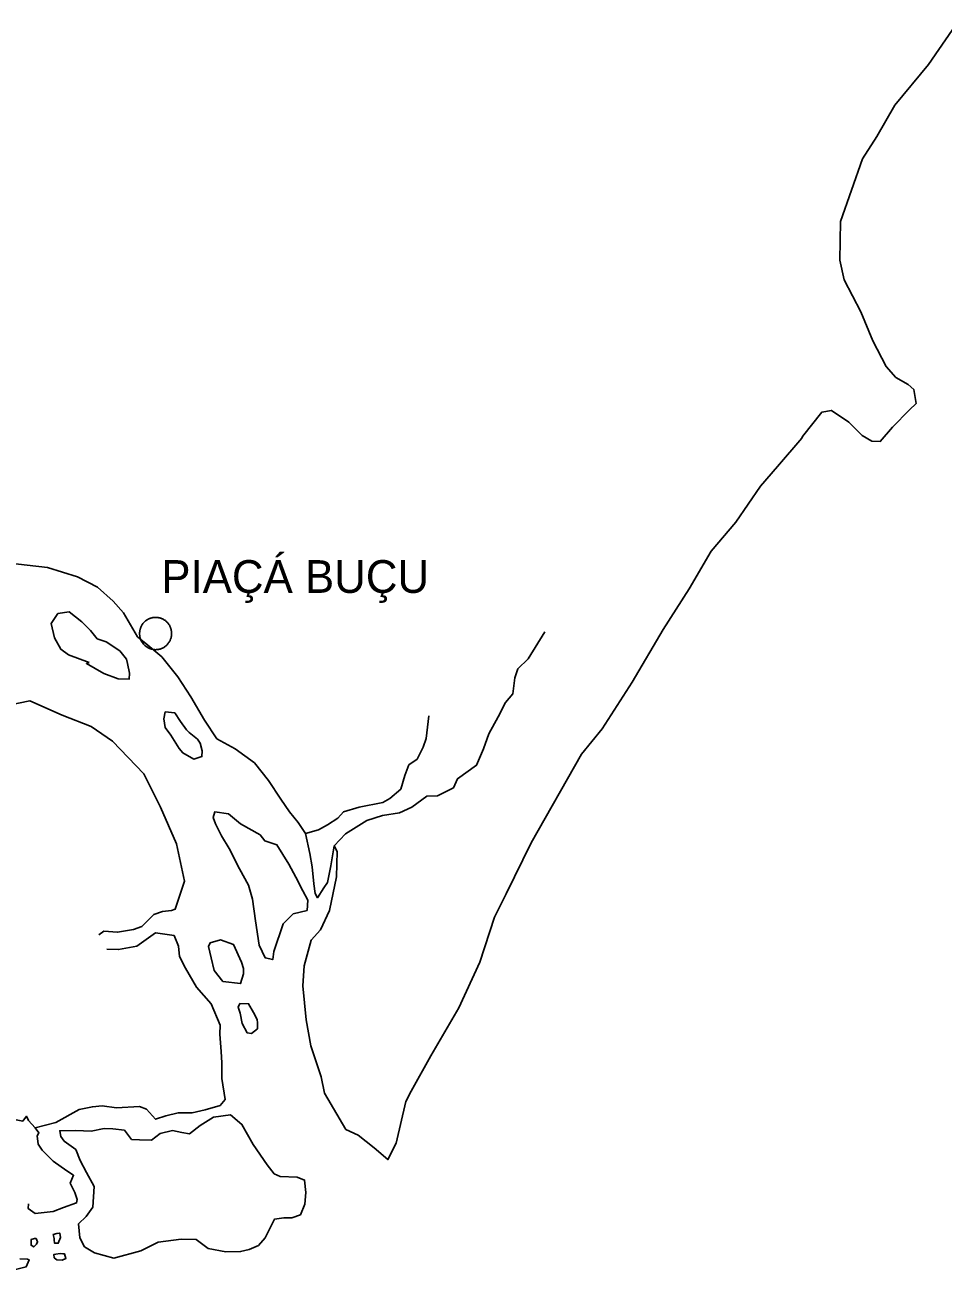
# Model space of a CAD drawing. Extents: x 662444 to 1640468, y 7452018 to 9606170.
# Drawn here: x 1438495 to 1457530, y 8823808 to 8849673 of the extents above; entities that cross this region are included whole.
import ezdxf

# ---------------------------------------------------------------- set-up
doc = ezdxf.new("R2010")
doc.units = 0
doc.layers.add('Level 1', color=7, linetype='Continuous')
doc.layers.add('Level 3', color=7, linetype='Continuous')

msp = doc.modelspace()

# ---------------------------------------------------------------- linework, layer by layer
at = {"layer": 'Level 1'}
for points in [[(1455855, 8841158), (1456051, 8841041), (1456229, 8841036), (1456480, 8841331), (1456834, 8841690), (1456970, 8841821), (1456923, 8842113), (1456804, 8842217), (1456553, 8842358), (1456349, 8842587), (1456075, 8843121), (1455826, 8843720), (1455479, 8844390), (1455390, 8844795), (1455401, 8845600), (1455858, 8846896), (1456159, 8847358), (1456531, 8848008), (1457230, 8848850), (1457795, 8849673)], [(1437449, 8838596), (1438961, 8838421), (1439586, 8838225), (1440001, 8838013), (1440325, 8837724), (1440540, 8837483), (1440826, 8836984), (1441042, 8836810), (1441335, 8836567), (1441667, 8836156), (1441932, 8835735), (1442218, 8835257), (1442473, 8834870), (1442854, 8834658), (1443256, 8834368), (1443545, 8834002), (1443800, 8833615), (1443981, 8833353), (1444163, 8833135), (1444312, 8832907), (1444400, 8832491), (1444448, 8832210), (1444483, 8831863), (1444510, 8831661), (1444563, 8831570), (1444691, 8831779), (1444771, 8831888), (1444836, 8832233), (1444903, 8832645), (1444966, 8832532), (1444952, 8832006), (1444811, 8831306), (1444623, 8830908), (1444428, 8830690), (1444281, 8830157), (1444259, 8829744), (1444328, 8829038), (1444424, 8828498), (1444638, 8827855), (1444706, 8827517), (1445151, 8826767), (1445402, 8826648), (1445738, 8826382), (1446019, 8826139), (1446194, 8826481), (1446395, 8827348), (1446501, 8827557), (1446908, 8828295), (1447489, 8829286), (1447925, 8830236), (1448227, 8831167), (1448473, 8831652), (1448990, 8832712), (1450037, 8834551), (1450461, 8835076), (1451085, 8836043), (1451724, 8837133), (1452268, 8837979), (1452722, 8838761), (1453236, 8839362), (1453744, 8840109), (1454099, 8840513), (1454602, 8841103), (1454614, 8841136), (1455016, 8841640), (1455216, 8841679), (1455575, 8841434), (1455855, 8841158)], [(1439826, 8836452), (1439398, 8836609), (1439236, 8836725), (1439109, 8836963), (1439040, 8837256), (1439178, 8837465), (1439412, 8837503), (1439672, 8837295), (1439855, 8837111), (1439994, 8836939), (1440181, 8836878), (1440463, 8836692), (1440603, 8836520), (1440622, 8836430), (1440661, 8836228), (1440658, 8836105), (1440425, 8836111), (1440130, 8836220), (1439770, 8836431), (1439826, 8836452)], [(1441536, 8837043), (1441536, 8837054), (1441535, 8837066), (1441534, 8837077), (1441534, 8837090), (1441532, 8837101), (1441530, 8837112), (1441528, 8837125), (1441525, 8837136), (1441522, 8837147), (1441519, 8837158), (1441515, 8837168), (1441511, 8837180), (1441507, 8837191), (1441501, 8837201), (1441496, 8837211), (1441490, 8837222), (1441484, 8837232), (1441478, 8837241), (1441471, 8837251), (1441464, 8837260), (1441457, 8837270), (1441449, 8837278), (1441441, 8837287), (1441433, 8837295), (1441424, 8837303), (1441416, 8837310), (1441406, 8837318), (1441397, 8837325), (1441387, 8837331), (1441378, 8837338), (1441368, 8837344), (1441358, 8837349), (1441347, 8837354), (1441336, 8837359), (1441326, 8837364), (1441315, 8837367), (1441304, 8837371), (1441293, 8837375), (1441281, 8837377), (1441270, 8837380), (1441259, 8837382), (1441247, 8837384), (1441236, 8837385), (1441224, 8837387), (1441213, 8837387), (1441202, 8837387), (1441190, 8837386), (1441179, 8837386), (1441166, 8837385), (1441155, 8837383), (1441144, 8837381), (1441132, 8837379), (1441121, 8837376), (1441110, 8837373), (1441098, 8837370), (1441088, 8837366), (1441077, 8837362), (1441066, 8837357), (1441056, 8837352), (1441046, 8837347), (1441036, 8837340), (1441026, 8837335), (1441017, 8837329), (1441006, 8837321), (1440997, 8837315), (1440988, 8837307), (1440980, 8837299), (1440971, 8837291), (1440963, 8837283), (1440955, 8837274), (1440948, 8837266), (1440940, 8837256), (1440934, 8837247), (1440928, 8837237), (1440921, 8837227), (1440915, 8837217), (1440909, 8837207), (1440904, 8837196), (1440900, 8837185), (1440895, 8837175), (1440891, 8837164), (1440888, 8837153), (1440884, 8837142), (1440882, 8837130), (1440879, 8837119), (1440877, 8837108), (1440875, 8837095), (1440874, 8837084), (1440872, 8837072), (1440872, 8837061), (1440872, 8837050), (1440872, 8837037), (1440873, 8837026), (1440874, 8837014), (1440876, 8837002), (1440878, 8836991), (1440880, 8836979), (1440883, 8836968), (1440886, 8836956), (1440889, 8836945)], [(1440889, 8836945), (1440893, 8836935), (1440897, 8836924), (1440901, 8836912), (1440906, 8836902), (1440912, 8836892), (1440918, 8836882), (1440923, 8836871), (1440930, 8836862), (1440937, 8836852), (1440944, 8836843), (1440951, 8836834), (1440959, 8836826), (1440967, 8836817), (1440975, 8836809), (1440983, 8836801), (1440992, 8836794), (1441002, 8836785), (1441010, 8836779), (1441020, 8836773), (1441030, 8836766), (1441040, 8836760), (1441050, 8836754), (1441061, 8836749), (1441071, 8836744), (1441081, 8836740), (1441092, 8836736), (1441103, 8836732), (1441114, 8836729), (1441126, 8836726), (1441137, 8836724), (1441148, 8836721), (1441160, 8836720), (1441172, 8836718), (1441184, 8836717), (1441195, 8836716), (1441206, 8836716), (1441218, 8836717), (1441229, 8836718), (1441241, 8836719), (1441252, 8836720), (1441264, 8836722), (1441276, 8836724), (1441287, 8836727), (1441298, 8836730), (1441309, 8836733), (1441319, 8836738), (1441330, 8836742), (1441342, 8836746), (1441352, 8836751), (1441362, 8836757), (1441372, 8836763), (1441382, 8836768), (1441391, 8836775), (1441401, 8836782), (1441410, 8836789), (1441419, 8836796), (1441427, 8836804), (1441436, 8836813), (1441444, 8836820), (1441452, 8836829), (1441459, 8836838), (1441467, 8836848), (1441474, 8836856), (1441480, 8836866), (1441487, 8836876), (1441493, 8836886), (1441499, 8836896), (1441503, 8836907), (1441508, 8836918), (1441513, 8836928), (1441516, 8836939), (1441520, 8836950), (1441524, 8836961), (1441526, 8836974), (1441529, 8836985), (1441531, 8836996), (1441533, 8837008), (1441534, 8837019), (1441535, 8837031), (1441536, 8837043)], [(1444903, 8832645), (1445142, 8832896), (1445581, 8833175), (1445905, 8833278), (1446261, 8833335), (1446519, 8833451), (1446824, 8833677), (1447046, 8833682), (1447382, 8833852), (1447465, 8834040), (1447860, 8834320), (1448003, 8834663), (1448111, 8834973), (1448309, 8835325), (1448461, 8835623), (1448610, 8835798), (1448652, 8836132), (1448712, 8836321), (1448928, 8836527), (1449276, 8837088)], [(1440026, 8830799), (1440128, 8830875), (1440415, 8830856), (1440749, 8830914), (1440916, 8830976), (1441167, 8831227), (1441345, 8831289), (1441534, 8831306), (1441612, 8831337), (1441805, 8831914), (1441638, 8832690), (1441305, 8833448), (1440958, 8834140), (1440313, 8834817), (1439867, 8835120), (1439265, 8835360), (1438598, 8835658), (1437551, 8835440)], [(1441523, 8834941), (1441405, 8835100), (1441377, 8835280), (1441403, 8835425), (1441602, 8835408), (1441719, 8835226), (1441847, 8835055), (1441901, 8834997), (1442074, 8834859), (1442127, 8834779), (1442167, 8834621), (1442164, 8834498), (1441996, 8834447), (1441767, 8834576), (1441692, 8834668), (1441523, 8834941)], [(1444312, 8832907), (1444580, 8832978), (1444771, 8833085), (1444985, 8833224), (1445099, 8833356), (1445423, 8833447), (1445913, 8833546), (1446059, 8833631), (1446286, 8833826), (1446371, 8834104), (1446454, 8834325), (1446624, 8834443), (1446752, 8834697), (1446813, 8834874), (1446870, 8835342)], [(1442942, 8832173), (1442732, 8832593), (1442573, 8832854), (1442447, 8833104), (1442395, 8833239), (1442431, 8833350), (1442718, 8833309), (1442967, 8833101), (1443370, 8832877), (1443467, 8832752), (1443719, 8832666), (1443963, 8832268), (1444110, 8831996), (1444257, 8831712), (1444363, 8831519), (1444346, 8831307), (1444056, 8831237), (1443851, 8831030), (1443658, 8830454), (1443631, 8830287), (1443477, 8830325), (1443352, 8830585), (1443277, 8831091), (1443212, 8831540), (1443131, 8831833), (1442942, 8832173)], [(1438710, 8826799), (1439134, 8826910), (1439617, 8827176), (1439895, 8827236), (1440095, 8827253), (1440393, 8827211), (1440869, 8827243), (1441012, 8827183), (1441205, 8826976), (1441417, 8827049), (1441674, 8827109), (1441961, 8827112), (1442229, 8827172), (1442541, 8827264), (1442644, 8827384), (1442579, 8827822), (1442576, 8828146), (1442561, 8828382), (1442537, 8828740), (1442543, 8828930), (1442356, 8829371), (1442055, 8829715), (1441822, 8830113), (1441696, 8830351), (1441680, 8830564), (1441586, 8830790), (1441201, 8830846), (1440817, 8830565), (1440438, 8830497), (1440195, 8830504)], [(1442988, 8830237), (1443029, 8830102), (1443026, 8829990), (1442965, 8829791), (1442601, 8829834), (1442419, 8830063), (1442359, 8830322), (1442300, 8830558), (1442335, 8830636), (1442547, 8830697), (1442821, 8830600), (1442988, 8830237)], [(1442959, 8829176), (1442918, 8829300), (1442953, 8829377), (1443130, 8829372), (1443236, 8829191), (1443309, 8829043), (1443319, 8828976), (1443315, 8828853), (1443191, 8828756), (1443103, 8828769), (1442997, 8828962), (1442959, 8829176)], [(1436396, 8826750), (1436661, 8826743), (1436993, 8826734), (1437374, 8826914), (1437730, 8826971), (1437977, 8827098), (1438103, 8827274), (1438173, 8826992), (1438448, 8826940), (1438529, 8827038), (1438570, 8826948), (1438710, 8826799)], [(1442044, 8824482), (1441734, 8824490), (1441257, 8824425), (1440898, 8824245), (1440340, 8824093), (1439934, 8824204), (1439727, 8824333), (1439632, 8824515), (1439607, 8824806), (1439766, 8824958), (1439905, 8825156), (1439927, 8825580), (1439769, 8825875), (1439643, 8826125), (1439550, 8826351), (1439311, 8826525), (1439236, 8826617), (1439218, 8826740), (1439550, 8826742), (1439870, 8826733), (1440137, 8826782), (1440314, 8826777), (1440557, 8826748), (1440707, 8826554), (1440872, 8826549), (1441116, 8826543), (1441297, 8826683), (1441553, 8826743), (1441751, 8826704), (1441905, 8826677), (1442131, 8826850), (1442402, 8827022), (1442757, 8827068), (1442995, 8826871), (1443227, 8826451), (1443514, 8826029), (1443664, 8825846), (1443784, 8825787), (1444138, 8825777), (1444292, 8825717), (1444318, 8825459), (1444300, 8825214), (1444205, 8824993), (1444026, 8824930), (1443860, 8824935), (1443672, 8824907), (1443473, 8824521), (1443335, 8824357), (1443145, 8824273), (1442967, 8824233), (1442657, 8824230), (1442293, 8824296), (1442044, 8824482)], [(1438710, 8826799), (1438785, 8826696), (1438750, 8826630), (1438767, 8826462), (1438852, 8826336), (1439079, 8826106), (1439361, 8825909), (1439502, 8825815), (1439431, 8825650), (1439526, 8825457), (1439577, 8825310), (1439564, 8825243), (1439296, 8825150), (1439083, 8825066), (1438706, 8825021), (1438565, 8825125), (1438567, 8825226)], [(1439101, 8824507), (1439081, 8824586), (1439159, 8824606), (1439215, 8824616), (1439234, 8824526), (1439187, 8824404), (1439109, 8824406), (1439100, 8824473), (1439101, 8824507)], [(1438732, 8824383), (1438676, 8824328), (1438621, 8824363), (1438625, 8824486), (1438692, 8824507), (1438725, 8824506), (1438756, 8824438), (1438732, 8824383)], [(1438392, 8824079), (1438547, 8824075), (1438580, 8824063), (1438521, 8823919), (1438086, 8823808)], [(1439266, 8824055), (1439155, 8824058), (1439101, 8824104), (1439092, 8824172), (1439136, 8824182), (1439225, 8824190), (1439280, 8824189), (1439314, 8824188), (1439344, 8824086), (1439266, 8824055)]]:
    msp.add_lwpolyline(points, dxfattribs=at)

# ---------------------------------------------------------------- texts
at = {"layer": 'Level 3'}
msp.add_text('PIAÇÁ BUÇU', height=679.3, dxfattribs=at).set_placement((1441322, 8837894))

doc.saveas('drawing.dxf')
